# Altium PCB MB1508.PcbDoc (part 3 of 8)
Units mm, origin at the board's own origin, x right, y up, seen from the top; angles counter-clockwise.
Board outline 129 x 77 mm, 4 copper layers (Top Layer, GND, POWER, Bottom Layer), stack 1.582 mm thick; 399 components, 297 nets, 1407 pads, 1316 vias.
Unrouted connection lines stored in the file: 535.
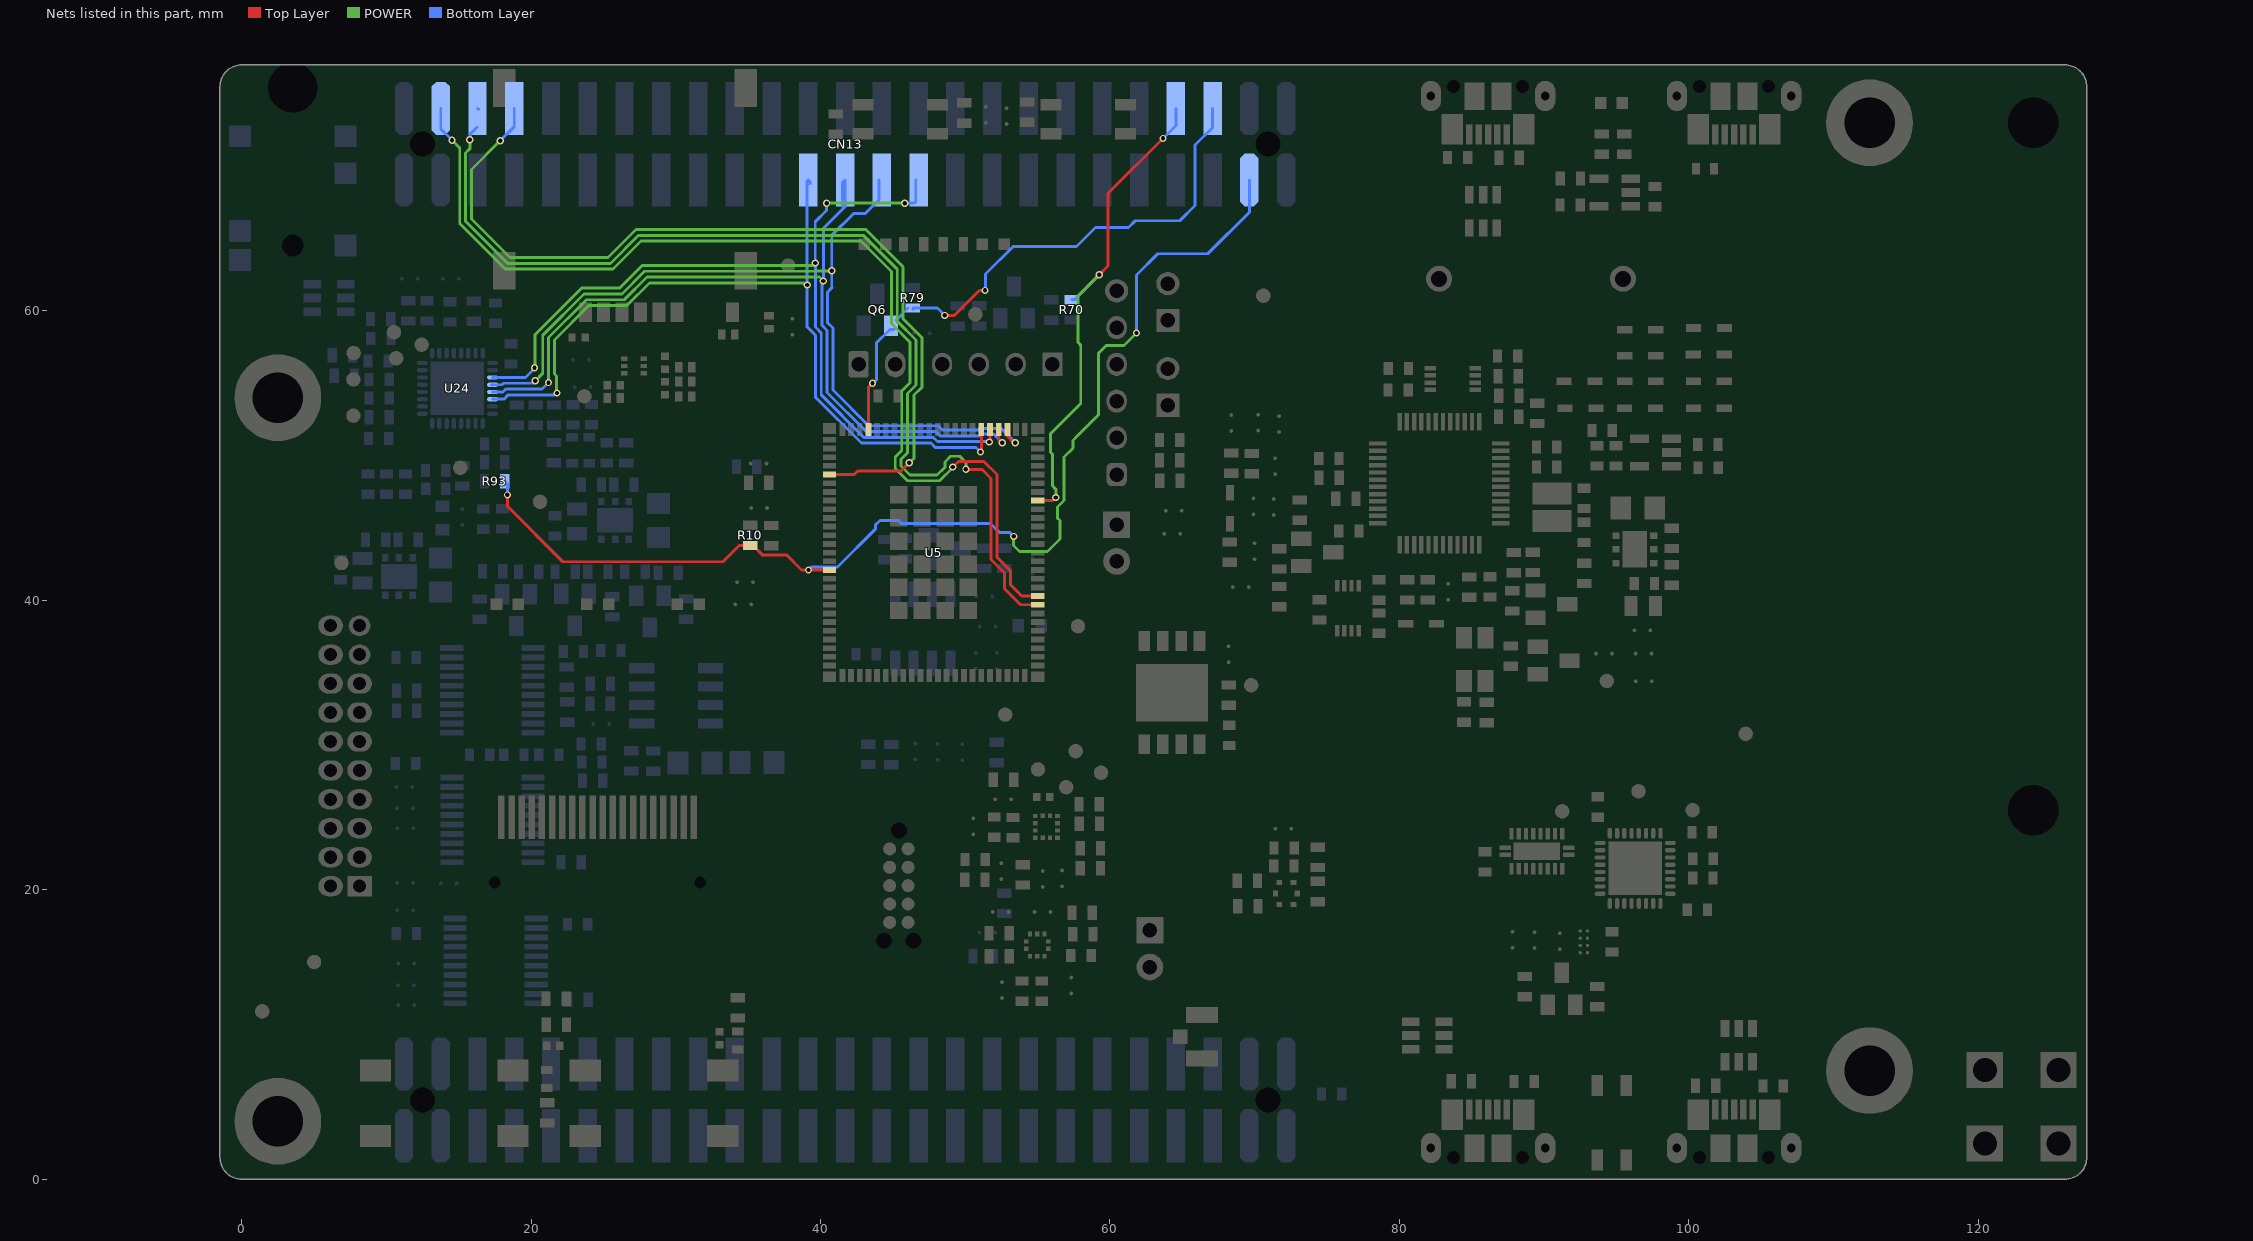
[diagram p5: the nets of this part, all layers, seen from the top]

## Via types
v1: diameter 0.5, hole 0.3, Top Layer to Bottom Layer, tented both sides, 1301 vias
v2: diameter 0.65, hole 0.4, Top Layer to Bottom Layer, tented both sides, 14 vias
v3: diameter 0.5/0.5/0.5/0.5 (per signal layer), hole 0.3, Top Layer to Bottom Layer, tented both sides, 1 vias

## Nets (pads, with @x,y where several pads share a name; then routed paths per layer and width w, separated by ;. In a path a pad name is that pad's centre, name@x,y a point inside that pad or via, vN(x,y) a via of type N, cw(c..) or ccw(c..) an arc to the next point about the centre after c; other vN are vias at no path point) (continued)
FFU_I2C0_SDA: CN13.3 R10.1 R93.1 U5.67 | length 80.2
  Top Layer w0.2: v1(18.365,47.284) 18.365,46.494 22.191,42.669 33.261,42.669 34.381,43.789 R10.1@34.843,43.789 ; R10.1@35.147,43.789 35.326,43.789 35.971,43.143 37.648,43.143 38.698,42.094 v1(39.172,42.094) U5.67@40.613,42.094
  POWER w0.2: v1(53.347,44.418) 53.347,43.794 53.76,43.381 55.686,43.381 56.541,44.236 56.541,45.507 56.379,45.67 56.379,46.445 56.823,46.89 56.823,49.898 57.441,50.515 57.441,51.04 57.621,51.221 57.621,51.232 59.223,52.834 59.223,57.094 59.748,57.619 60.982,57.619 v1(61.835,58.472)
  Bottom Layer w0.2: R93.1@18.18,48.231 18.365,48.046 v1(18.365,47.284) ; v1(39.172,42.094) 39.368,42.29 40.88,42.29 40.884,42.294 41.164,42.294 43.787,44.917 43.787,45.197 44.11,45.519 44.711,45.519 45.376,45.519 45.592,45.303 45.619,45.303 45.621,45.302 51.749,45.302 52.352,44.699 53.066,44.699 v1(53.347,44.418) ; v1(61.835,58.472) 61.835,62.474 63.309,63.947 66.764,63.947 69.64,66.823 CN13.3@69.64,69.045
FFU_PCM_CLK: CN13.27 U5.34 U24.30 | length 57.7
  Top Layer w0.2: v1(51.06,50.247) 51.113,50.3 U5.34@51.113,51.794
  POWER w0.2: 21.756,55.487 21.61,55.632 21.61,57.992 23.988,60.37 26.606,60.37 28.174,61.938 38.928,61.938 v1(39.078,61.788) ; 21.761,55.487 21.761,54.355 v1(21.788,54.328)
  Bottom Layer w0.2: U24.30@17.338,53.9 18.121,53.9 18.421,54.2 21.66,54.2 v1(21.788,54.328) ; 39.087,61.303 39.078,61.312 ; CN13.27@39.224,68.791 39.319,68.886 CN13.27@39.16,69.045 39.078,68.963 v1(39.078,61.788) 39.078,61.312 ; v1(51.06,50.247) 50.741,50.566 47.926,50.566 47.629,50.862 42.829,50.862 39.655,54.036 39.655,58.313 39.078,58.89 39.078,61.312
FFU_PCM_FS: CN13.25 U5.32 U24.29 | length 60.4
  Top Layer w0.2: U5.32@52.313,51.794 52.313,51.141 v1(52.563,50.891)
  POWER w0.2: v1(21.206,55.046) 21.21,55.051 21.21,58.158 23.822,60.77 26.44,60.77 28.008,62.338 39.925,62.338 v1(40.196,62.067)
  Bottom Layer w0.2: U24.29@17.338,54.4 18.055,54.4 18.255,54.6 20.76,54.6 v1(21.206,55.046) ; CN13.25@41.5,67.745 41.5,68.845 CN13.25@41.7,69.045 41.7,67.193 40.196,65.688 v1(40.196,62.067) 40.096,61.967 40.096,59.004 40.455,58.644 40.455,54.367 43.16,51.662 47.961,51.662 48.257,51.366 51.072,51.366 51.193,51.487 51.967,51.487 v1(52.563,50.891) ; 41.555,67.101 CN13.25@41.555,67.902
FFU_PCM_IN: CN13.21 U5.33 U24.27 | length 62.3
  Top Layer w0.2: v1@51.698,50.937 51.713,50.952 U5.33@51.713,51.794
  POWER w0.2: v1(20.235,56.072) 20.26,56.098 20.26,58.33 20.256,58.334 23.491,61.57 26.109,61.57 27.677,63.138 39.509,63.138 v1@39.683,63.312 ; v1(40.421,67.447) v1(45.821,67.447)
  Bottom Layer w0.2: U24.27@17.338,55.4 19.612,55.4 v1@20.23,56.018 ; v1(39.637,63.312) 39.637,66.156 40.421,66.94 v1(40.421,67.447) ; v1@39.778,63.306 39.646,63.174 39.646,58.888 40.055,58.479 40.055,54.201 42.994,51.262 47.795,51.262 48.091,50.966 51.634,50.966 v1(51.663,50.937) v1@51.715,50.989 ; v1(45.821,67.447) 46.494,67.447 46.58,67.532 CN13.21@46.58,69.045
FFU_PCM_OUT: CN13.23 U5.31 U24.28 | length 60.4
  Top Layer w0.2: U5.31@52.913,51.794 52.913,51.318 53.341,50.891 v1(53.463,50.891)
  POWER w0.2: v1(20.289,55.166) 20.81,55.687 20.81,58.323 23.657,61.17 26.274,61.17 27.842,62.738 39.675,62.738 39.683,62.747 40.748,62.747 v3(40.78,62.778)
  Bottom Layer w0.2: U24.28@17.255,54.9 17.293,54.862 17.344,54.913 U24.28@17.357,54.9 ; U24.28@17.338,54.9 U24.28@17.357,54.9 ; v1(20.289,55.166) 20.123,55 18.09,55 17.99,54.9 U24.28@17.357,54.9 ; CN13.23@44.04,69.045 44.04,67.685 43.095,66.74 42.294,66.74 40.78,65.226 v3(40.78,62.778) 40.78,61.601 40.783,61.597 40.496,61.31 40.496,59.169 40.855,58.81 40.855,54.533 43.326,52.062 48.126,52.062 48.423,51.766 50.906,51.766 51.027,51.887 52.467,51.887 v1(53.463,50.891)
FFU_PSM_IND: CN13.6 Q6.1 R79.2 U5.47 | length 39.8
  Top Layer w0.2: U5.47@43.313,51.794 43.313,54.726 v1(43.591,55.005) ; v1(48.584,59.69) 49.247,59.69 50.974,61.417 v1(51.363,61.417)
  Bottom Layer w0.2: v1@43.634,55.005 43.856,55.227 43.856,57.772 44.802,58.718 Q6.1@45.079,58.718 ; Q6.1@45.231,59.378 R79.2@46.056,60.204 ; R79.2@46.38,60.114 R79.2@46.464,60.197 ; R79.2@46.38,60.197 R79.2@46.464,60.197 ; v1(48.584,59.69) 48.076,60.197 R79.2@46.464,60.197 ; v1@51.403,61.407 51.403,62.54 53.316,64.453 57.682,64.453 58.993,65.765 61.282,65.765 61.749,66.231 64.83,66.231 65.881,67.282 65.881,71.459 67.1,72.678 CN13.6@67.1,73.995
FFU_RFFE_SCLK: CN13.46 U5.8 | length 73.2
  Top Layer w0.2: v1(50.047,49.053) 51.158,49.053 51.788,48.424 51.788,42.814 52.716,41.886 52.716,40.806 53.829,39.694 U5.8@55.013,39.694
  POWER w0.2: v1(15.769,71.82) 15.769,71.207 15.475,70.913 15.475,66.193 18.382,63.285 25.485,63.285 27.423,65.223 42.959,65.223 45.301,62.881 45.301,59.288 46.604,57.985 46.604,54.885 46.015,54.296 46.015,50.196 45.565,49.747 45.565,49.282 46.186,48.661 48.06,48.661 48.597,49.198 48.597,49.558 48.992,49.953 49.621,49.953 50.047,49.527 v1(50.047,49.053)
  Bottom Layer w0.2: v1(15.769,71.82) 15.769,72.2 CN13.46@16.262,72.693 ; CN13.46@16.3,73.995 CN13.46@16.364,73.931
FFU_RFFE_SDATA: CN13.48 U5.9 | length 74.4
  Top Layer w0.2: v1(49.147,49.216) 49.534,49.603 51.285,49.603 52.188,48.701 52.188,42.98 53.116,42.051 53.116,41.084 53.907,40.294 U5.9@55.013,40.294
  POWER w0.2: v1(14.531,71.799) 15.068,71.263 15.068,66.034 18.217,62.885 25.651,62.885 27.589,64.823 42.793,64.823 44.901,62.715 44.901,59.122 46.174,57.849 46.174,55.021 45.615,54.462 45.615,50.362 45.165,49.912 45.165,49.112 46.016,48.261 48.226,48.261 49.147,49.182 v1(49.147,49.216)
  Bottom Layer w0.2: CN13.48@13.76,73.995 13.76,72.571 v1(14.531,71.799)
FFU_RFFE_VDDIO: CN13.44 U5.56 | length 62.1
  Top Layer w0.2: U5.56@40.613,48.694 42.33,48.694 42.58,48.943 45.561,48.943 v1(46.13,49.512) 46.061,49.512 v1@46.042,49.493
  POWER w0.2: v1(17.875,71.766) 15.875,69.765 15.875,66.359 18.548,63.685 25.32,63.685 27.258,65.623 43.125,65.623 45.701,63.047 45.701,59.453 47.004,58.151 47.004,54.72 46.471,54.187 46.471,49.821 46.162,49.512 v1(46.13,49.512)
  Bottom Layer w0.2: v1(17.875,71.766) 18.84,72.731 CN13.44@18.84,73.995
FFU_TX_IND: CN13.8 R70.2 U5.20 | length 34.9
  Top Layer w0.2: U5.20@55.013,46.894 56.05,46.894 v1(56.262,47.106) ; v1(59.268,62.5) 59.878,63.11 59.878,68.135 v1(63.665,71.922) ; v1@63.613,71.974 v1@63.671,72.032
  POWER w0.2: v1(56.262,47.106) 56.262,47.675 56.044,47.892 56.044,50.073 55.889,50.228 55.889,51.508 57.985,53.604 57.985,55.067 57.987,55.068 57.987,57.632 57.806,57.813 57.806,61.038 v1(59.268,62.5)
  Bottom Layer w0.2: R70.2@57.37,60.775 57.71,60.775 57.71,60.942 v1(59.268,62.5) ; v1(63.665,71.922) 64.56,72.817 CN13.8@64.56,73.995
